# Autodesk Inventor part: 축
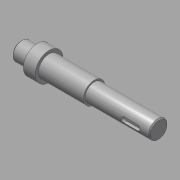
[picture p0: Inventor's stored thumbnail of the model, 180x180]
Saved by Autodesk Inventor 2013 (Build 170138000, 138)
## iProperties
Created: 2015-09
Part Number: 축
Material: 강철, 연강
Document SubType Name: Modeling
Designer: mduedu
Density: 1 g/cm^3
Author: mduedu
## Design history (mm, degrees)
sketch "스케치1"
  geometry: L1 (-64, 0)-(64, 0); L2 (-64, 0)-(-64, 8.5); L3 (-64, 8.5)-(-49, 8.5); L4 (-49, 8.5)-(-49, 13); L5 (-49, 13)-(-38, 13); L6 (-38, 13)-(-38, 10); L7 (-38, 10)-(4, 10); L8 (4, 10)-(4, 8.5); L9 (4, 8.5)-(64, 8.5); L10 (64, 8.5)-(64, 0); 2 further points
  constraints: 20 end point, 5 parallel, 2 horizontal, 2 perpendicular, 1 coincident, 1 midpoint, 1 vertical
  dimensions: "d0" = 128 distance of L1.start L1.end; "d2" = 11 distance of L4.end L5.end; "d3" = 42 distance of L6.end L7.end; "d4" = 60 distance of L8.end L9.end; "d5" = 17 diameter of L3 L1; "d6" = 17 diameter of L9 L1; "d7" = 20 diameter of L7 L1; "d8" = 26 diameter of L5 L1
revolve "회전1" sketch "스케치1" stored, may be unused: angle "d9" = 90 deg
node "작업 평면1"
sketch "스케치2"
  geometry: L1 (5.5, 2.5)-(18.5, 2.5); L2 (18.5, -2.5)-(5.5, -2.5); L3 (5.5, 2.5)-(18.5, -2.5); L4 (18.5, 2.5)-(5.5, -2.5); L5 (30, -8.5)-(30, 8.5) reference; A1 r 2.5 centre (5.5, 0) between (5.5, 2.5) and (5.5, -2.5); A2 r 2.5 centre (18.5, 0) between (18.5, -2.5) and (18.5, 2.5); 2 further points
  constraints: 8 end point, 4 point on circle, 4 tangent, 2 centre point, 2 midpoint, 1 horizontal, 1 horizontal alignment, 1 parallel
  dimensions: "d10" = 18 dimension on A2 A1; "d12" = 9 distance edge to line of A2 L5; "d13" = 5 distance between parallel lines of L2 L1
extrude "돌출1" cut sketch "스케치2" distance "d14" = 3; taper "d15" = 0 deg
node "작업 평면2"
sketch "스케치4"
  geometry: L1 (7, -3)-(-9, -3); L2 (-9, 3)-(7, 3); L3 (-21, 10)-(-21, -10) reference; A1 r 3 centre (-9, 0) between (-9, 3) and (-9, -3); A2 r 3 centre (7, 0) between (7, -3) and (7, 3); 1 further point
  constraints: 4 end point, 4 point on circle, 4 tangent, 2 centre point, 1 horizontal, 1 horizontal alignment, 1 parallel
  dimensions: "d16" = 22 dimension on A1 A2; "d18" = 6 distance between parallel lines of L2 L1; "d19" = 9 distance edge to line of A1 L3
extrude "돌출2" cut sketch "스케치4" distance "d20" = 3.5; taper "d21" = 0 deg
sketch "스케치5"
  geometry: L1 (4, 8.5)-(64, 8.5) reference; L2 (4, -8.5)-(64, -8.5) reference; L3 (37, 8.5)-(37, -8.5); L4 (37, -6.5)-(35, -8.5); L5 (37, -8.5)-(35, -8.5); L6 (37, -8.5)-(37, -6.5); L7 (4, -10)-(4, 10) reference; 1 further point
  constraints: 8 end point, 4 point on line, 1 collinear, 1 perpendicular
  dimensions: "d22" = 4 diameter of L4.end L3; "d24" = 45 deg angle of L3 L4; "d26" = 33 distance between parallel lines of L3 L7
revolve "회전2" sketch "스케치5" stored, may be unused: angle "d27" = 90 deg
chamfer "모따기1" distance "d28" = 1; stored, may be unused: second distance "d29" = 2, angle "d30" = 45 deg
node "솔리드1"
